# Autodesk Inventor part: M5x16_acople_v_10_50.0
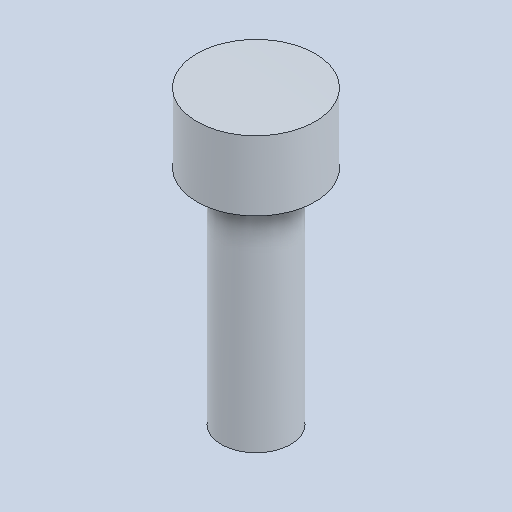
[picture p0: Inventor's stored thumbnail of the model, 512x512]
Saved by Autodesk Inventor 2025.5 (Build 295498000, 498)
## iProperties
Created: 2026-10
Part Number: M5x16_acople_v_10_50.0
Material: Genérico
Document SubType Name: Modeling
Designer: Luis M
Density: 1 g/cm^3
Appearance: Valor por defecto
Author: Luis M
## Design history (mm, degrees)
feature "Base1"
node "Sólido1"
